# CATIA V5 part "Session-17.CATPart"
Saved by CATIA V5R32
Part number: Part1
Bounding box of the stored display mesh (mm): x -30 to 30, y -62.5 to 62.5, z 0 to 20
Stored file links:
  D:\Amoozesh\Masterdcam\Mastercam Course\Videos\Session-17\Session-17.CATPart
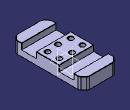
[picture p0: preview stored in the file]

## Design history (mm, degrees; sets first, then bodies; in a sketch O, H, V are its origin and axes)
Body1 (main body)
  Sketch1 on xy-plane, origin (0, 0, 0), H (0, 1, 0), V (-1, 0, 0)
    line L1 (62.5, 30) -> (62.5, -30)
    line L2 (62.5, -30) -> (-62.5, -30)
    line L3 (-62.5, -30) -> (-62.5, 30)
    line L4 (-62.5, 30) -> (62.5, 30)
    length L2 = 125
    length L1 = 60
    vertical: L1 V, L3 V
    horizontal: L2 H, L4 H
    equidistance: L1 L3 O, L2 L4 O
  Pad1: profile Sketch1, direction (0, 0, 1), length 20
  Chamfer1: length 8, angle 45, on edge [face of Pad1 from Sketch1.L1 | face of Pad1 from Sketch1.L2]; edge [face of Pad1 from Sketch1.L4 | face of Pad1 from Sketch1.L1]; edge [face of Pad1 from Sketch1.L2 | face of Pad1 from Sketch1.L3]; edge [face of Pad1 from Sketch1.L3 | face of Pad1 from Sketch1.L4]
  Sketch2 on end face of Pad1, origin (0, 0, 20), H (0, 1, 0), V (-1, 0, 0)
    point P1 (20, -34.8308)
    line L1 (20, -34.8308) -> (45, -34.8308)
    line L2 (45, -34.8308) -> (45, 38.388)
    line L3 (45, 38.388) -> (20, 38.388)
    line L4 (20, 38.388) -> (20, -34.8308)
    point P2 (45, -34.8308)
    point P3 (45, 38.388)
    point P4 (20, 38.388)
    point P5 (-20, -34.8308)
    point P6 (-45, -34.8308)
    point P7 (-45, 38.388)
    point P8 (-20, 38.388)
    line L5 (-20, -34.8308) -> (-45, -34.8308)
    line L6 (-45, -34.8308) -> (-45, 38.388)
    line L7 (-45, 38.388) -> (-20, 38.388)
    line L8 (-20, 38.388) -> (-20, -34.8308)
    distance P1 V = 20
    distance L2 L4 = 25
    horizontal: L1 H, L3 H
    vertical: L2 V, L4 V
    symmetry: P1 P5 V, P2 P6 V, P3 P7 V, P4 P8 V, L1 L5 V, L2 L6 V, L3 L7 V, L4 L8 V
  Pocket1: profile Sketch2, direction (0, 0, -1), length 10
  Sketch3 on end face of Pad1, origin (0, 0, 20), H (0, 1, 0), V (-1, 0, 0)
    circle A1 centre (12, 0) radius 4
    point P1 (12, 0)
    circle A2 centre (10, 20) radius 4
    point P2 (10, 20)
    circle A3 centre (10, -20) radius 4
    circle A4 centre (-10, -20) radius 4
    circle A5 centre (-12, 0) radius 4
    circle A6 centre (-10, 20) radius 4
    radius A1 = 4
    distance P1 V = 12
    radius A2 = 4
    distance P2 H = 20
    distance V P2 = 10
    coincidence: P1 H
    symmetry: A2 A3 H, A3 A4 V, A1 A5 V, A2 A6 V
  Pocket2: profile Sketch3, direction (0, 0, -1), through (limit type 6)
  Chamfer2: length 0.5, angle 45, on edge [end face of Pad1 | face of Pocket2 from Sketch3.A2]; edge [end face of Pad1 | face of Pocket2 from Sketch3.A1]; edge [end face of Pad1 | face of Pocket2 from Sketch3.A3]; edge [end face of Pad1 | face of Pocket2 from Sketch3.A4]; edge [end face of Pad1 | face of Pocket2 from Sketch3.A5]; edge [end face of Pad1 | face of Pocket2 from Sketch3.A6]
  Fillet1: radius 5, on edge [face of Pad1 from Sketch1.L1 | face of Chamfer1]; edge [face of Chamfer1 | face of Pad1 from Sketch1.L2]; edge [face of Pad1 from Sketch1.L2 | face of Chamfer1]; edge [face of Chamfer1 | face of Pad1 from Sketch1.L3]; edge [face of Pad1 from Sketch1.L3 | face of Chamfer1]; edge [face of Chamfer1 | face of Pad1 from Sketch1.L4]; edge [face of Chamfer1 | face of Pad1 from Sketch1.L1]; edge [face of Pad1 from Sketch1.L4 | face of Chamfer1]
  Chamfer3: length 0.5, angle 45, on end face of Pad1 (x2); edge [face of Pad1 from Sketch1.L2 | end face of Pad1]; edge [end face of Pad1 | face of Pocket1 from Sketch2.L4]; edge [face of Pad1 from Sketch1.L4 | end face of Pad1]; edge [end face of Pad1 | face of Pocket1 from Sketch2.L8]; edge [face of Pocket1 from Sketch2.L2 | face of Pad1 from Sketch1.L2]; edge [face of Pad1 from Sketch1.L2 | face of Pocket1 from Sketch2.L4]; edge [face of Pocket1 from Sketch2.L4 | face of Pad1 from Sketch1.L4]; edge [face of Pad1 from Sketch1.L2 | face of Pocket1 from Sketch2.L6]; edge [face of Pocket1 from Sketch2.L8 | face of Pad1 from Sketch1.L2]; edge [face of Pocket1 from Sketch2.L6 | face of Pad1 from Sketch1.L4]; edge [face of Pad1 from Sketch1.L4 | face of Pocket1 from Sketch2.L8]; edge [face of Pad1 from Sketch1.L4 | face of Pocket1 from Sketch2.L2]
